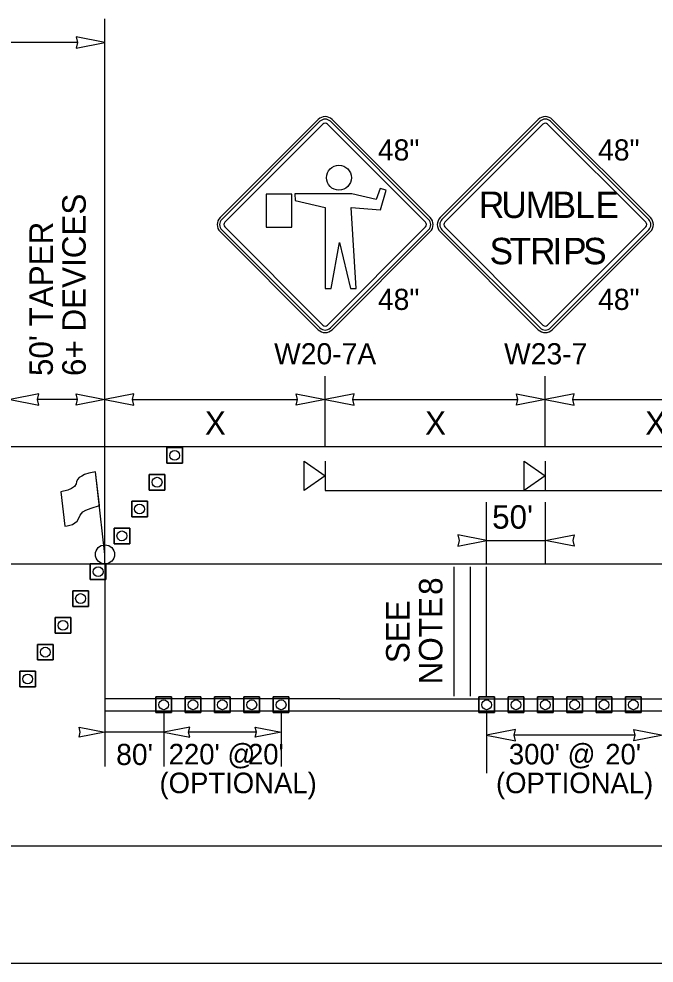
# Model space of a CAD drawing. Extents: x 99999.1 to 100095.7, y 99995 to 100010.7.
# Drawn here: x 100051.18 to 100053.344, y 100005.732 to 100008.949 of the extents above; entities that cross this region are included whole.
import ezdxf

# ---------------------------------------------------------------- set-up
doc = ezdxf.new("R2010")
doc.units = 0
for name, color, linetype in [('Default', 7, 'Continuous'), ('RD_ED_ShoulderPavedEdge', 7, 'Continuous'), ('RD_MK_LineDblYellowCenter', 7, 'Continuous'), ('RD_MK_LineEdgeWhite', 7, 'Continuous'), ('RD_MK_LineNoPass', 7, 'Continuous'), ('RD_MK_LineSkipCenter', 7, 'Continuous'), ('TR_SN_ConstructionSigns', 7, 'Continuous'), ('TR_WZ_FlaggingStation', 7, 'Continuous'), ('TR_WZ_PortableSignMountBlk-Org', 7, 'Continuous'), ('TR_WZ_TrafficCone', 7, 'Continuous'), ('TR_WZ_WorkZoneDetails', 7, 'Continuous'), ('TR_WZ_WorkZoneTextCurrent', 7, 'Continuous')]:
    doc.layers.add(name, color=color, linetype=linetype)

msp = doc.modelspace()

# ---------------------------------------------------------------- linework, layer by layer
at = {"layer": 'Default'}
for p, q in [((100052.9495, 100008.6062), (100052.6154, 100008.2721)), ((100053.3313, 100008.2721), (100052.9972, 100008.6062)), ((100052.6154, 100008.2243), (100052.9495, 100007.8902)), ((100052.9972, 100007.8902), (100053.3313, 100008.2243))]:
    msp.add_line(p, q, dxfattribs=at)
for centre, start, end in [((100052.9733, 100008.5823), 45, 135), ((100052.6392, 100008.2482), 135, 225), ((100053.3075, 100008.2482), 315, 45), ((100052.9733, 100007.9141), 225, 315)]:
    msp.add_arc(centre, 0.0338, start, end, dxfattribs=at)
at = {"layer": 'RD_ED_ShoulderPavedEdge'}
for p, q in [((100040.1076, 100007.4923), (100055.6424, 100007.4923)), ((100040.1076, 100005.7323), (100055.6424, 100005.7323))]:
    msp.add_line(p, q, dxfattribs=at)
at = {"layer": 'RD_MK_LineDblYellowCenter'}
for p, q in [((100052.2733, 100006.6323), (100055.6631, 100006.6323)), ((100052.2733, 100006.5923), (100055.6218, 100006.5923))]:
    msp.add_line(p, q, dxfattribs=at)
at = {"layer": 'RD_MK_LineEdgeWhite'}
for p, q in [((100040.1076, 100007.0923), (100055.6424, 100007.0923)), ((100040.1076, 100006.1323), (100055.6424, 100006.1323))]:
    msp.add_line(p, q, dxfattribs=at)
at = {"layer": 'RD_MK_LineNoPass'}
msp.add_line((100051.4733, 100006.5923), (100052.2733, 100006.5923), dxfattribs=at)
at = {"layer": 'RD_MK_LineSkipCenter'}
msp.add_lwpolyline([(100052.2733, 100006.6323), (100051.4733, 100006.6323)], dxfattribs=at)
at = {"layer": 'TR_SN_ConstructionSigns'}
for p, q in [((100052.1995, 100008.6062), (100051.8654, 100008.2721)), ((100052.2055, 100008.6002), (100051.8713, 100008.2661)), ((100052.5754, 100008.2661), (100052.2412, 100008.6002)), ((100052.5813, 100008.2721), (100052.2472, 100008.6062)), ((100052.6154, 100008.2721), (100052.9495, 100008.6062)), ((100052.9555, 100008.6002), (100052.6213, 100008.2661)), ((100053.3254, 100008.2661), (100052.9912, 100008.6002)), ((100052.9972, 100008.6062), (100053.3313, 100008.2721)), ((100051.8813, 100008.2561), (100052.2154, 100008.5903)), ((100052.2313, 100008.5903), (100052.5654, 100008.2561)), ((100052.6313, 100008.2561), (100052.9654, 100008.5903)), ((100052.9813, 100008.5903), (100053.3154, 100008.2561)), ((100052.2154, 100007.9061), (100051.8813, 100008.2402)), ((100052.5654, 100008.2402), (100052.2313, 100007.9061)), ((100052.9654, 100007.9061), (100052.6313, 100008.2402)), ((100053.3154, 100008.2402), (100052.9813, 100007.9061)), ((100051.8654, 100008.2243), (100052.1995, 100007.8902)), ((100051.8713, 100008.2303), (100052.2055, 100007.8962)), ((100052.2412, 100007.8962), (100052.5754, 100008.2303)), ((100052.2472, 100007.8902), (100052.5813, 100008.2243)), ((100052.9495, 100007.8902), (100052.6154, 100008.2243)), ((100052.6213, 100008.2303), (100052.9555, 100007.8962)), ((100052.9912, 100007.8962), (100053.3254, 100008.2303)), ((100053.3313, 100008.2243), (100052.9972, 100007.8902))]:
    msp.add_line(p, q, dxfattribs=at)
for points in [[(100052.12, 100008.3526), (100052.1213, 100008.3309), (100052.2239, 100008.307), (100052.2239, 100008.0307), (100052.2439, 100008.0307), (100052.272, 100008.1877), (100052.3095, 100008.0307), (100052.3285, 100008.0307), (100052.3119, 100008.3069), (100052.4122, 100008.2988), (100052.4311, 100008.3658), (100052.4104, 100008.3717), (100052.3972, 100008.3334), (100052.3143, 100008.3526)], [(100052.0221, 100008.3523), (100052.0221, 100008.2401), (100052.1097, 100008.2401), (100052.1097, 100008.3523)]]:
    msp.add_lwpolyline(points, close=True, dxfattribs=at)
msp.add_circle((100052.2703, 100008.4081), 0.0424, dxfattribs=at)
for centre, radius, start, end in [((100052.2233, 100008.5823), 0.0338, 45, 135), ((100052.2233, 100008.5823), 0.0253, 45, 135), ((100052.2233, 100008.5823), 0.0113, 45, 135), ((100052.9733, 100008.5823), 0.0338, 45, 135), ((100052.9733, 100008.5823), 0.0253, 45, 135), ((100052.9733, 100008.5823), 0.0113, 45, 135), ((100051.8892, 100008.2482), 0.0338, 135, 225), ((100052.5575, 100008.2482), 0.0338, 315, 45), ((100052.6392, 100008.2482), 0.0338, 135, 225), ((100053.3075, 100008.2482), 0.0338, 315, 45), ((100051.8892, 100008.2482), 0.0253, 135, 225), ((100051.8892, 100008.2482), 0.0113, 135, 225), ((100052.5575, 100008.2482), 0.0113, 315, 45), ((100052.5575, 100008.2482), 0.0253, 315, 45), ((100052.6392, 100008.2482), 0.0253, 135, 225), ((100052.6392, 100008.2482), 0.0113, 135, 225), ((100053.3075, 100008.2482), 0.0113, 315, 45), ((100053.3075, 100008.2482), 0.0253, 315, 45), ((100052.2233, 100007.9141), 0.0338, 225, 315), ((100052.2233, 100007.9141), 0.0253, 225, 315), ((100052.2233, 100007.9141), 0.0113, 225, 315), ((100052.9733, 100007.9141), 0.0338, 225, 315), ((100052.9733, 100007.9141), 0.0253, 225, 315), ((100052.9733, 100007.9141), 0.0113, 225, 315)]:
    msp.add_arc(centre, radius, start, end, dxfattribs=at)
at = {"layer": 'TR_WZ_FlaggingStation'}
for p, q in [((100051.4543, 100007.2917), (100051.4413, 100007.4061)), ((100051.4733, 100007.1248), (100051.4413, 100007.4058)), ((100051.3233, 100007.3383), (100051.3366, 100007.2211)), ((100051.4543, 100007.2917), (100051.4543, 100007.2917))]:
    msp.add_line(p, q, dxfattribs=at)
for points in [[(100051.4413, 100007.4061), (100051.4355, 100007.4048), (100051.4177, 100007.4014), (100051.4039, 100007.3972), (100051.3942, 100007.3911), (100051.3857, 100007.3864), (100051.38, 100007.3796), (100051.3757, 100007.3717), (100051.3752, 100007.3655), (100051.3698, 100007.3563), (100051.359, 100007.3489), (100051.3466, 100007.3437), (100051.3233, 100007.3383)], [(100051.3366, 100007.2211), (100051.3448, 100007.2225), (100051.3624, 100007.2271), (100051.3781, 100007.2376), (100051.3846, 100007.2482), (100051.3885, 100007.2585), (100051.3976, 100007.2694), (100051.4086, 100007.2756), (100051.4259, 100007.2827), (100051.4543, 100007.2917)]]:
    msp.add_lwpolyline(points, dxfattribs=at)
msp.add_circle((100051.4733, 100007.1248), 0.0325, dxfattribs=at)
at = {"layer": 'TR_WZ_PortableSignMountBlk-Org'}
for p, q in [((100052.2233, 100007.4422), (100052.2233, 100007.3422)), ((100052.9733, 100007.4422), (100052.9733, 100007.3422))]:
    msp.add_line(p, q, dxfattribs=at)
for points in [[(100052.2233, 100007.3923), (100052.1515, 100007.3422), (100052.1515, 100007.4422)], [(100052.9733, 100007.3923), (100052.9015, 100007.3422), (100052.9015, 100007.4422)]]:
    msp.add_lwpolyline(points, close=True, dxfattribs=at)
at = {"layer": 'TR_WZ_TrafficCone'}
for points in [[(100051.6843, 100007.4886), (100051.7376, 100007.4886), (100051.7376, 100007.4352), (100051.6843, 100007.4352), (100051.6843, 100007.4886)], [(100051.6843, 100007.4352), (100051.7376, 100007.4352), (100051.7376, 100007.4886), (100051.6843, 100007.4886), (100051.6843, 100007.4352)], [(100051.6243, 100007.3972), (100051.6776, 100007.3972), (100051.6776, 100007.3439), (100051.6243, 100007.3439), (100051.6243, 100007.3972)], [(100051.6243, 100007.3439), (100051.6776, 100007.3439), (100051.6776, 100007.3972), (100051.6243, 100007.3972), (100051.6243, 100007.3439)], [(100051.5643, 100007.3059), (100051.6176, 100007.3059), (100051.6176, 100007.2526), (100051.5643, 100007.2526), (100051.5643, 100007.3059)], [(100051.5643, 100007.2526), (100051.6176, 100007.2526), (100051.6176, 100007.3059), (100051.5643, 100007.3059), (100051.5643, 100007.2526)], [(100051.5043, 100007.2146), (100051.5576, 100007.2146), (100051.5576, 100007.1612), (100051.5043, 100007.1612), (100051.5043, 100007.2146)], [(100051.5043, 100007.1612), (100051.5576, 100007.1612), (100051.5576, 100007.2146), (100051.5043, 100007.2146), (100051.5043, 100007.1612)], [(100051.4766, 100007.0923), (100051.4233, 100007.0923), (100051.4233, 100007.039), (100051.4766, 100007.039), (100051.4766, 100007.0923)], [(100051.4766, 100007.039), (100051.4233, 100007.039), (100051.4233, 100007.0923), (100051.4766, 100007.0923), (100051.4766, 100007.039)], [(100051.4166, 100007.001), (100051.3633, 100007.001), (100051.3633, 100006.9477), (100051.4166, 100006.9477), (100051.4166, 100007.001)], [(100051.4166, 100006.9477), (100051.3633, 100006.9477), (100051.3633, 100007.001), (100051.4166, 100007.001), (100051.4166, 100006.9477)], [(100051.3566, 100006.9097), (100051.3033, 100006.9097), (100051.3033, 100006.8563), (100051.3566, 100006.8563), (100051.3566, 100006.9097)], [(100051.3566, 100006.8563), (100051.3033, 100006.8563), (100051.3033, 100006.9097), (100051.3566, 100006.9097), (100051.3566, 100006.8563)], [(100051.2966, 100006.8183), (100051.2433, 100006.8183), (100051.2433, 100006.765), (100051.2966, 100006.765), (100051.2966, 100006.8183)], [(100051.2966, 100006.765), (100051.2433, 100006.765), (100051.2433, 100006.8183), (100051.2966, 100006.8183), (100051.2966, 100006.765)], [(100051.2366, 100006.727), (100051.1833, 100006.727), (100051.1833, 100006.6737), (100051.2366, 100006.6737), (100051.2366, 100006.727)], [(100051.2366, 100006.6737), (100051.1833, 100006.6737), (100051.1833, 100006.727), (100051.2366, 100006.727), (100051.2366, 100006.6737)], [(100051.7, 100006.639), (100051.6467, 100006.639), (100051.6467, 100006.5857), (100051.7, 100006.5857), (100051.7, 100006.639)], [(100051.7, 100006.5857), (100051.6467, 100006.5857), (100051.6467, 100006.639), (100051.7, 100006.639), (100051.7, 100006.5857)], [(100051.8, 100006.639), (100051.7467, 100006.639), (100051.7467, 100006.5857), (100051.8, 100006.5857), (100051.8, 100006.639)], [(100051.8, 100006.5857), (100051.7467, 100006.5857), (100051.7467, 100006.639), (100051.8, 100006.639), (100051.8, 100006.5857)], [(100051.9, 100006.639), (100051.8467, 100006.639), (100051.8467, 100006.5857), (100051.9, 100006.5857), (100051.9, 100006.639)], [(100051.9, 100006.5857), (100051.8467, 100006.5857), (100051.8467, 100006.639), (100051.9, 100006.639), (100051.9, 100006.5857)], [(100052, 100006.639), (100051.9467, 100006.639), (100051.9467, 100006.5857), (100052, 100006.5857), (100052, 100006.639)], [(100052, 100006.5857), (100051.9467, 100006.5857), (100051.9467, 100006.639), (100052, 100006.639), (100052, 100006.5857)], [(100052.1, 100006.639), (100052.0467, 100006.639), (100052.0467, 100006.5857), (100052.1, 100006.5857), (100052.1, 100006.639)], [(100052.1, 100006.5857), (100052.0467, 100006.5857), (100052.0467, 100006.639), (100052.1, 100006.639), (100052.1, 100006.5857)], [(100052.8, 100006.5857), (100052.7467, 100006.5857), (100052.7467, 100006.639), (100052.8, 100006.639), (100052.8, 100006.5857)], [(100052.8, 100006.639), (100052.7467, 100006.639), (100052.7467, 100006.5857), (100052.8, 100006.5857), (100052.8, 100006.639)], [(100052.9, 100006.5857), (100052.8467, 100006.5857), (100052.8467, 100006.639), (100052.9, 100006.639), (100052.9, 100006.5857)], [(100052.9, 100006.639), (100052.8467, 100006.639), (100052.8467, 100006.5857), (100052.9, 100006.5857), (100052.9, 100006.639)], [(100053, 100006.5857), (100052.9467, 100006.5857), (100052.9467, 100006.639), (100053, 100006.639), (100053, 100006.5857)], [(100053, 100006.639), (100052.9467, 100006.639), (100052.9467, 100006.5857), (100053, 100006.5857), (100053, 100006.639)], [(100053.1, 100006.5857), (100053.0467, 100006.5857), (100053.0467, 100006.639), (100053.1, 100006.639), (100053.1, 100006.5857)], [(100053.1, 100006.639), (100053.0467, 100006.639), (100053.0467, 100006.5857), (100053.1, 100006.5857), (100053.1, 100006.639)], [(100053.2, 100006.5857), (100053.1467, 100006.5857), (100053.1467, 100006.639), (100053.2, 100006.639), (100053.2, 100006.5857)], [(100053.2, 100006.639), (100053.1467, 100006.639), (100053.1467, 100006.5857), (100053.2, 100006.5857), (100053.2, 100006.639)], [(100053.3, 100006.5857), (100053.2467, 100006.5857), (100053.2467, 100006.639), (100053.3, 100006.639), (100053.3, 100006.5857)], [(100053.3, 100006.639), (100053.2467, 100006.639), (100053.2467, 100006.5857), (100053.3, 100006.5857), (100053.3, 100006.639)]]:
    msp.add_lwpolyline(points, dxfattribs=at)
for centre in [(100051.7109, 100007.4619), (100051.6509, 100007.3706), (100051.5909, 100007.2792), (100051.5309, 100007.1879), (100051.45, 100007.0657), (100051.39, 100006.9743), (100051.33, 100006.883), (100051.27, 100006.7917), (100051.21, 100006.7003), (100051.6733, 100006.6123), (100051.7733, 100006.6123), (100051.8733, 100006.6123), (100051.9733, 100006.6123), (100052.0733, 100006.6123), (100052.7733, 100006.6123), (100052.8733, 100006.6123), (100052.9733, 100006.6123), (100053.0733, 100006.6123), (100053.1733, 100006.6123), (100053.2733, 100006.6123)]:
    msp.add_circle(centre, 0.0167, dxfattribs=at)
at = {"layer": 'TR_WZ_WorkZoneDetails'}
for p, q in [((100051.4733, 100007.0923), (100051.4733, 100008.9491)), ((100051.3796, 100008.8691), (100044.3704, 100008.8691)), ((100052.2233, 100007.4923), (100052.2233, 100007.7323)), ((100052.9733, 100007.4923), (100052.9733, 100007.7323)), ((100051.3796, 100007.6523), (100051.2437, 100007.6523)), ((100051.5671, 100007.6523), (100052.1296, 100007.6523)), ((100052.3171, 100007.6523), (100052.8796, 100007.6523)), ((100053.0671, 100007.6523), (100053.6296, 100007.6523)), ((100052.2233, 100007.3422), (100055.2233, 100007.3422)), ((100052.7733, 100007.0923), (100052.7733, 100007.3023)), ((100052.9733, 100007.3023), (100052.9733, 100007.0923)), ((100052.7733, 100007.1723), (100052.9733, 100007.1723)), ((100051.4733, 100007.0923), (100051.4733, 100006.4023)), ((100052.6628, 100006.6423), (100052.6628, 100007.0823)), ((100052.7185, 100006.6423), (100052.7185, 100007.0823)), ((100052.7733, 100006.6423), (100052.7733, 100007.0823)), ((100051.6733, 100006.5857), (100051.6733, 100006.4023)), ((100052.0733, 100006.5857), (100052.0733, 100006.4023)), ((100052.7733, 100006.589), (100052.7733, 100006.379)), ((100051.6733, 100006.5193), (100051.4733, 100006.5193)), ((100051.989, 100006.5193), (100051.7577, 100006.5193)), ((100053.2796, 100006.509), (100052.8671, 100006.509))]:
    msp.add_line(p, q, dxfattribs=at)
for points in [[(100051.4733, 100008.8691), (100051.3751, 100008.8884), (100051.3796, 100008.8691), (100051.3751, 100008.8498)], [(100051.15, 100007.6523), (100051.2483, 100007.6331), (100051.2437, 100007.6523), (100051.2483, 100007.6716)], [(100051.4733, 100007.6523), (100051.3751, 100007.6331), (100051.3796, 100007.6523), (100051.3751, 100007.6716)], [(100051.4733, 100007.6523), (100051.5716, 100007.6331), (100051.5671, 100007.6523), (100051.5716, 100007.6716)], [(100052.2233, 100007.6523), (100052.1251, 100007.6331), (100052.1296, 100007.6523), (100052.1251, 100007.6716)], [(100052.2233, 100007.6523), (100052.3216, 100007.6331), (100052.3171, 100007.6523), (100052.3216, 100007.6716)], [(100052.9733, 100007.6523), (100052.8751, 100007.6331), (100052.8796, 100007.6523), (100052.8751, 100007.6716)], [(100052.9733, 100007.6523), (100053.0716, 100007.6331), (100053.0671, 100007.6523), (100053.0716, 100007.6716)], [(100052.7733, 100007.1723), (100052.6751, 100007.1916), (100052.6796, 100007.1723), (100052.6751, 100007.1531)], [(100052.9733, 100007.1723), (100053.0716, 100007.1916), (100053.0671, 100007.1723), (100053.0716, 100007.1531)], [(100051.4733, 100006.5193), (100051.3849, 100006.502), (100051.389, 100006.5193), (100051.3849, 100006.5367)], [(100051.6733, 100006.5193), (100051.7618, 100006.502), (100051.7577, 100006.5193), (100051.7618, 100006.5367)], [(100052.0733, 100006.5193), (100051.9849, 100006.502), (100051.989, 100006.5193), (100051.9849, 100006.5367)], [(100052.7733, 100006.509), (100052.8716, 100006.4897), (100052.8671, 100006.509), (100052.8716, 100006.5283)], [(100053.3733, 100006.509), (100053.2751, 100006.4897), (100053.2796, 100006.509), (100053.2751, 100006.5283)]]:
    msp.add_lwpolyline(points, close=True, dxfattribs=at)

# ---------------------------------------------------------------- texts
at = {"layer": 'Default'}
for s, p in [('R', (100052.747, 100008.2707)), ('U', (100052.8235, 100008.2707)), ('M', (100052.9063, 100008.2707)), ('B', (100052.9981, 100008.2707)), ('L', (100053.0746, 100008.2707)), ('E', (100053.1439, 100008.2707)), ('S', (100052.7834, 100008.1132)), ('T', (100052.8518, 100008.1132)), ('R', (100052.9211, 100008.1132)), ('I', (100052.9976, 100008.1132)), ('P', (100053.0336, 100008.1132)), ('S', (100053.102, 100008.1132))]:
    msp.add_text(s, height=0.09, dxfattribs=at).set_placement(p)
at = {"layer": 'TR_SN_ConstructionSigns'}
for s, p in [('48"', (100052.4031, 100008.4667)), ('48"', (100053.1531, 100008.4667)), ('48"', (100052.4031, 100007.9576)), ('48"', (100053.1531, 100007.9576)), ('W20-7A', (100052.0494, 100007.7723)), ('W23-7', (100052.8328, 100007.7723))]:
    msp.add_text(s, height=0.072, rotation=360, dxfattribs=at).set_placement(p)
at = {"layer": 'TR_WZ_WorkZoneDetails'}
for s, p in [('8', (100052.6228, 100006.9868)), ('SEE', (100052.5108, 100006.7544)), ('NOTE', (100052.6228, 100006.682))]:
    msp.add_text(s, height=0.08, rotation=90, dxfattribs=at).set_placement(p)
at = {"layer": 'TR_WZ_WorkZoneTextCurrent'}
for s, p in [('6+ DEVICES', (100051.4077, 100007.7323)), ("50' TAPER", (100051.2957, 100007.7323))]:
    msp.add_text(s, height=0.08, rotation=90, dxfattribs=at).set_placement(p)
for s, height, p in [('X', 0.08, (100051.8136, 100007.5323)), ('X', 0.08, (100052.5636, 100007.5323)), ('X', 0.08, (100053.3136, 100007.5323)), ("50'", 0.08, (100052.7921, 100007.2123)), ("80'", 0.072, (100051.5114, 100006.4073)), ("220' @", 0.07, (100051.6903, 100006.4093)), ("20'", 0.07, (100051.9604, 100006.4093)), ("300' @", 0.07, (100052.8491, 100006.4093)), ("20'", 0.07, (100053.1775, 100006.4093)), ('(OPTIONAL)', 0.07, (100051.659, 100006.3113)), ('(OPTIONAL)', 0.07, (100052.8053, 100006.3113))]:
    msp.add_text(s, height=height, dxfattribs=at).set_placement(p)

doc.saveas('drawing.dxf')
